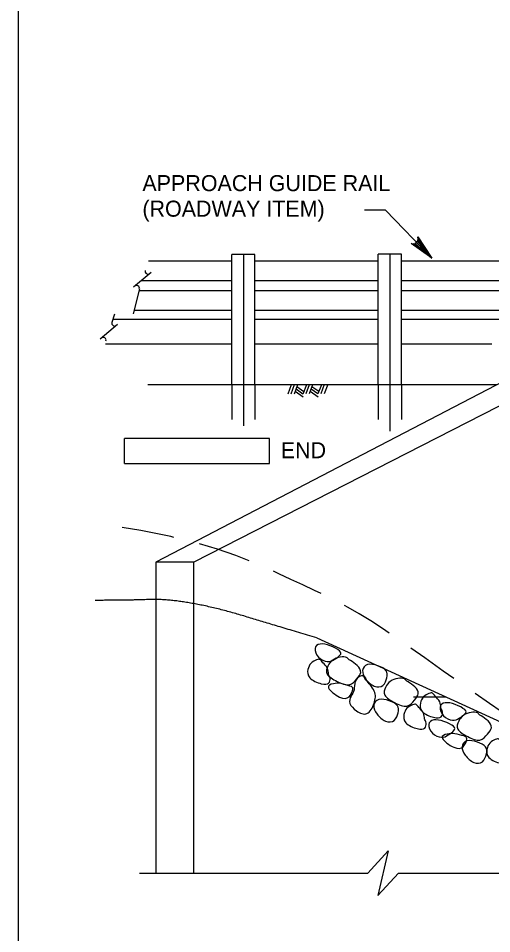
# Model space of a CAD drawing. Extents: x 638263 to 640391, y 293683 to 298655.
# Drawn here: x 638475.5 to 638564, y 297381.1 to 297552.4 of the extents above; entities that cross this region are included whole.
import ezdxf

# ---------------------------------------------------------------- set-up
doc = ezdxf.new("R2010")
doc.units = 0
for name, color, linetype in [('2', 7, 'Continuous'), ('3', 7, 'Continuous'), ('4', 7, 'Continuous'), ('8', 7, 'Continuous')]:
    doc.layers.add(name, color=color, linetype=linetype)

msp = doc.modelspace()

# ---------------------------------------------------------------- linework, layer by layer
at = {"layer": '2'}
for p, q in [((638475.46, 297262.46), (638475.46, 297826.46)), ((638499.81, 297506.98), (638515.38, 297506.98)), ((638519.71, 297506.98), (638542.78, 297506.98)), ((638547.1, 297506.98), (638572.78, 297506.98)), ((638498.46, 297503.28), (638515.38, 297503.28)), ((638519.71, 297503.28), (638542.78, 297503.28)), ((638547.1, 297503.28), (638583.44, 297503.28)), ((638498.01, 297501.43), (638515.38, 297501.43)), ((638519.71, 297501.43), (638542.78, 297501.43)), ((638547.1, 297501.43), (638583.44, 297501.43)), ((638497.09, 297497.74), (638515.38, 297497.74)), ((638519.71, 297497.74), (638542.78, 297497.74)), ((638547.1, 297497.74), (638585.74, 297497.74)), ((638493.16, 297496.08), (638515.38, 297496.08)), ((638519.71, 297496.08), (638542.78, 297496.08)), ((638547.1, 297496.08), (638585.74, 297496.08)), ((638491.76, 297491.46), (638515.38, 297491.46)), ((638519.71, 297491.46), (638542.78, 297491.46)), ((638547.1, 297491.46), (638564.01, 297491.46))]:
    msp.add_line(p, q, dxfattribs=at)
at = {"layer": '3'}
for p, q in [((638519.71, 297508.16), (638515.38, 297508.16)), ((638515.38, 297483.77), (638515.38, 297508.16)), ((638517.55, 297508.16), (638517.55, 297476.08)), ((638519.71, 297483.77), (638519.71, 297508.16)), ((638542.78, 297483.77), (638542.78, 297508.24)), ((638547.1, 297508.24), (638542.78, 297508.24)), ((638544.94, 297508.24), (638544.94, 297475.12)), ((638547.1, 297483.77), (638547.1, 297508.24)), ((638500.27, 297504.8), (638497, 297502.06)), ((638498.09, 297501.72), (638496.92, 297497.05)), ((638493.46, 297497.02), (638492.96, 297495.47)), ((638494.03, 297495.08), (638490.76, 297492.34)), ((638564.89, 297483.77), (638499.7, 297483.77)), ((638566.28, 297484.49), (638501.15, 297450.61)), ((638574.49, 297484.49), (638508.29, 297450.61)), ((638515.38, 297483.77), (638515.38, 297477.28)), ((638519.71, 297483.77), (638519.71, 297477.28)), ((638526.51, 297483.77), (638525.84, 297482.02)), ((638527.06, 297483.78), (638526.39, 297482.02)), ((638527.69, 297483.79), (638527.03, 297482.03)), ((638527.56, 297483.45), (638528.85, 297482.55)), ((638529.32, 297483.79), (638528.66, 297482.06)), ((638529.87, 297483.8), (638529.21, 297482.07)), ((638530.5, 297483.8), (638529.85, 297482.08)), ((638530.37, 297483.46), (638531.66, 297482.56)), ((638532.13, 297483.8), (638531.48, 297482.07)), ((638532.68, 297483.81), (638532.02, 297482.08)), ((638533.31, 297483.81), (638532.66, 297482.09)), ((638542.78, 297483.77), (638542.78, 297477.28)), ((638547.1, 297483.77), (638547.1, 297477.28)), ((638527.23, 297482.57), (638528.73, 297481.53)), ((638527.4, 297483.02), (638528.69, 297482.12)), ((638530.04, 297482.58), (638531.54, 297481.54)), ((638530.21, 297483.03), (638531.5, 297482.13)), ((638508.29, 297450.61), (638501.15, 297450.61)), ((638501.15, 297450.61), (638501.15, 297443.49)), ((638508.29, 297442.74), (638508.29, 297450.61)), ((638501.15, 297443.49), (638501.15, 297392.39)), ((638508.29, 297392.39), (638508.29, 297442.74)), ((638531.31, 297436.44), (638572.69, 297417.47)), ((638549.34, 297425.38), (638555.44, 297425.38)), ((638540.8, 297392.39), (638544.64, 297396.56)), ((638544.64, 297396.56), (638542.71, 297388.22)), ((638498.11, 297392.39), (638540.8, 297392.39)), ((638542.71, 297388.22), (638546.56, 297392.39)), ((638546.56, 297392.39), (638585.75, 297392.39))]:
    msp.add_line(p, q, dxfattribs=at)
for centre, start, end in [((638499.71, 297505.03), 162.1496, 312.1496), ((638497.56, 297501.84), 347.4782, 130.0168), ((638497.56, 297501.84), 130.0028, 130.0168), ((638493.47, 297495.31), 162.1496, 312.1496), ((638491.33, 297492.12), 347.4782, 130.0168), ((638491.32, 297492.12), 130.0028, 130.0168)]:
    msp.add_arc(centre, 0.533, start, end, dxfattribs=at)
for points, degree in [([(638531.31, 297436.44), (638522.78, 297438.93), (638512.86, 297441.99), (638503.33, 297443.74), (638495.98, 297443.45), (638489.83, 297443.45)], 2), ([(638535.6, 297433.18), (638535.36, 297432.92), (638534.49, 297432.37), (638533.39, 297431.72), (638531.4, 297432.66), (638530.64, 297434.59), (638531.73, 297435.49), (638533.75, 297435.06), (638535.93, 297433.91), (638535.84, 297433.43), (638535.6, 297433.18)], 3), ([(638533.48, 297429.68), (638533.54, 297429.38), (638533.85, 297429.01), (638533.69, 297427.79), (638532.35, 297427.62), (638529.46, 297428.87), (638529.55, 297430.62), (638530.06, 297431.73), (638531.32, 297432.43), (638531.98, 297432.46), (638532.28, 297431.85), (638533.45, 297430.82), (638533.41, 297429.98), (638533.48, 297429.68)], 3), ([(638537.01, 297432.62), (638537.07, 297432.54), (638537.4, 297432.25), (638538.99, 297431.33), (638539.78, 297429.9), (638538.78, 297428.85), (638537.57, 297427.22), (638535, 297428.22), (638532.78, 297429.63), (638533.32, 297431.23), (638534.11, 297432.36), (638535.72, 297432.97), (638537.06, 297432.76), (638536.96, 297432.71), (638537.01, 297432.62)], 3), ([(638544.24, 297430.28), (638544.52, 297429.91), (638544.48, 297429.07), (638543.85, 297427.24), (638542.01, 297427.11), (638540.26, 297428.73), (638539.57, 297430.37), (638540.53, 297431.71), (638542.81, 297431.3), (638543.96, 297430.65), (638544.24, 297430.28)], 3), ([(638539.92, 297429.31), (638540.06, 297429.22), (638540.17, 297428.77), (638542.43, 297426.46), (638542.18, 297424.24), (638540.78, 297421.66), (638538.58, 297422.67), (638537.17, 297424.18), (638537.64, 297425.55), (638538.39, 297426.57), (638538.25, 297428.4), (638539.34, 297429.31), (638539.78, 297429.4), (638539.92, 297429.31)], 3), ([(638547.79, 297428.64), (638547.84, 297428.55), (638548.17, 297428.27), (638549.76, 297427.35), (638550.55, 297425.92), (638549.55, 297424.87), (638548.35, 297423.24), (638545.77, 297424.24), (638543.55, 297425.65), (638544.1, 297427.25), (638544.89, 297428.38), (638546.49, 297428.99), (638547.84, 297428.78), (638547.73, 297428.72), (638547.79, 297428.64)], 3), ([(638537.47, 297427.4), (638537.89, 297427.25), (638538.19, 297427.15), (638537.49, 297425.09), (638535.76, 297424.92), (638532.64, 297427.38), (638534.49, 297427.91), (638535.67, 297428.01), (638537.05, 297427.54), (638537.47, 297427.4)], 3), ([(638546.34, 297423.73), (638546.62, 297423.36), (638546.58, 297422.52), (638545.95, 297420.69), (638544.11, 297420.56), (638542.37, 297422.18), (638541.67, 297423.82), (638542.64, 297425.16), (638544.91, 297424.75), (638546.06, 297424.1), (638546.34, 297423.73)], 3), ([(638554.5, 297423.39), (638554.57, 297423.08), (638554.87, 297422.72), (638554.72, 297421.49), (638553.38, 297421.33), (638550.48, 297422.58), (638550.58, 297424.33), (638551.09, 297425.43), (638552.35, 297426.14), (638553, 297426.17), (638553.3, 297425.56), (638554.47, 297424.52), (638554.44, 297423.69), (638554.5, 297423.39)], 3), ([(638551.44, 297421.27), (638551.5, 297420.97), (638551.81, 297420.6), (638551.65, 297419.37), (638550.31, 297419.21), (638547.42, 297420.46), (638547.51, 297422.21), (638548.02, 297423.31), (638549.28, 297424.02), (638549.94, 297424.05), (638550.23, 297423.44), (638551.41, 297422.41), (638551.37, 297421.57), (638551.44, 297421.27)], 3), ([(638558.99, 297422.2), (638558.75, 297421.94), (638557.88, 297421.38), (638556.78, 297420.74), (638554.79, 297421.68), (638554.03, 297423.61), (638555.12, 297424.51), (638557.14, 297424.07), (638559.32, 297422.93), (638559.23, 297422.45), (638558.99, 297422.2)], 3), ([(638561.45, 297422.28), (638561.51, 297422.2), (638561.84, 297421.91), (638563.43, 297420.99), (638564.22, 297419.56), (638563.22, 297418.51), (638562.02, 297416.88), (638559.44, 297417.88), (638557.22, 297419.3), (638557.77, 297420.89), (638558.55, 297422.02), (638560.16, 297422.63), (638561.5, 297422.42), (638561.4, 297422.37), (638561.45, 297422.28)], 3), ([(638556.9, 297419.08), (638556.67, 297418.81), (638555.82, 297418.24), (638554.73, 297417.57), (638552.72, 297418.45), (638551.92, 297420.36), (638552.98, 297421.29), (638555.01, 297420.91), (638557.22, 297419.82), (638557.14, 297419.34), (638556.9, 297419.08)], 3), ([(638558.77, 297418.07), (638559.19, 297417.93), (638559.49, 297417.84), (638558.84, 297415.76), (638557.13, 297415.54), (638553.94, 297417.93), (638555.77, 297418.5), (638556.96, 297418.63), (638558.34, 297418.2), (638558.77, 297418.07)], 3), ([(638562.84, 297416.02), (638563.12, 297415.64), (638563.08, 297414.81), (638562.45, 297412.98), (638560.61, 297412.84), (638558.86, 297414.47), (638558.16, 297416.1), (638559.13, 297417.44), (638561.4, 297417.03), (638562.56, 297416.39), (638562.84, 297416.02)], 3), ([(638566.97, 297414.83), (638567.05, 297414.53), (638567.36, 297414.18), (638567.24, 297412.95), (638565.9, 297412.74), (638562.97, 297413.92), (638563.02, 297415.68), (638563.5, 297416.79), (638564.75, 297417.53), (638565.4, 297417.58), (638565.71, 297416.97), (638566.91, 297415.97), (638566.9, 297415.13), (638566.97, 297414.83)], 3)]:
    msp.add_open_spline(points, degree=degree, dxfattribs=at)
at = {"layer": '4'}
for p, q in [((638544.12, 297516.44), (638540.18, 297516.44)), ((638552.77, 297507.48), (638544.12, 297516.44)), ((638522.44, 297473.76), (638495.29, 297473.76)), ((638495.29, 297469.05), (638495.29, 297473.76)), ((638522.44, 297469.05), (638522.44, 297473.76)), ((638495.29, 297469.05), (638522.44, 297469.05))]:
    msp.add_line(p, q, dxfattribs=at)
msp.add_lwpolyline([(638552.77, 297507.48), (638548.9, 297510.23), (638549.33, 297510.14), (638549.69, 297510.22), (638549.95, 297510.4), (638550.13, 297510.66), (638550.23, 297511.01), (638550.16, 297511.44), (638552.77, 297507.48), (638550.23, 297511.01), (638550.13, 297510.66), (638552.77, 297507.48), (638549.95, 297510.4), (638549.69, 297510.22), (638552.77, 297507.48), (638549.33, 297510.14)], dxfattribs=at)
at = {"layer": '8'}
for p, q in [((638498.36, 297456.49), (638494.89, 297457.06)), ((638503.95, 297455.37), (638498.36, 297456.49)), ((638504.56, 297455.22), (638503.95, 297455.37)), ((638512.72, 297453.04), (638509.33, 297454.03)), ((638516.15, 297451.85), (638512.72, 297453.04)), ((638518.65, 297450.87), (638516.15, 297451.85)), ((638524.16, 297448.42), (638523.15, 297448.88)), ((638526.45, 297447.36), (638524.16, 297448.42)), ((638528.67, 297446.34), (638526.45, 297447.36)), ((638530.83, 297445.32), (638528.67, 297446.34)), ((638532.07, 297444.72), (638530.83, 297445.32)), ((638537.13, 297442.13), (638536.45, 297442.49)), ((638539.23, 297440.93), (638537.13, 297442.13)), ((638541.36, 297439.64), (638539.23, 297440.93)), ((638543.55, 297438.21), (638541.36, 297439.64)), ((638544.84, 297437.34), (638543.55, 297438.21)), ((638551.47, 297432.67), (638548.87, 297434.52)), ((638554.9, 297430.22), (638551.47, 297432.67)), ((638556.89, 297428.82), (638554.9, 297430.22)), ((638563.57, 297424.14), (638560.92, 297425.99)), ((638569.02, 297420.4), (638563.57, 297424.14))]:
    msp.add_line(p, q, dxfattribs=at)

# ---------------------------------------------------------------- texts
at = {"layer": '4'}
for s, p in [('APPROACH GUIDE RAIL', (638498.66, 297520.02)), ('(ROADWAY ITEM)', (638498.66, 297515.24)), ('END', (638524.54, 297470.04))]:
    msp.add_text(s, height=3, dxfattribs=at).set_placement(p)

doc.saveas('drawing.dxf')
